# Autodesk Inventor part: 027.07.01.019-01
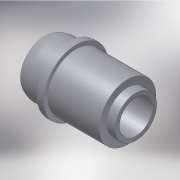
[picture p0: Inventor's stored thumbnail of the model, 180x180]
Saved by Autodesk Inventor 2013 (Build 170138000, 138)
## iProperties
Shininess: 25.0
Length Units: 11269
Angle Units: 11279
Time Units: 11290
Mass Units: 11283
Length Display Precision: 3
Angle Display Precision: 2
Created: 2001-11
Part Number: 027.07.01.019-01
Document SubType Name: Modeling
Designer: SOleg
Material: Steel, Mild
Density: 7.86 g/cm^3
Density: 0.0
Volumn: 0.0
Area: 0.0
PropertySet Name: Model Information
Control State: 0
Master: False
Checked Out: True
Checked Out Date: 2008-10-15
Last Check In Date: 2008-10-15
Author: SOleg
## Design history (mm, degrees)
body "Solid1"
revolve "RevolutionAngle1" stored, may be unused: angle "d24" = 360 deg
sketch "Sketch1"
  geometry: L1 (-25.5, 16.5)-(-19.232, 16.5); L2 (-32.5, 14.624)-(-32.5, 10); L3 (-32.5, 10)-(22.5, 10); L4 (22.5, 12.5)-(22.5, 10); L5 (22.5, 12.5)-(17.5, 12.5); L6 (17.5, 12.5)-(17.5, 17); L7 (17.5, 17)-(-13.5, 17); L8 (-13.5, 17)-(-13.5, 19.5); L9 (-13.5, 19.5)-(-17.5, 19.5); L10 (-19.232, 16.5)-(-17.5, 19.5); L11 (-27.5, 0)-(27.5, 0); L12 (-27.5, 0)-(27.5, 0); A1 r 14 centre (-25.5, 2.5) between (-25.5, 16.5) and (-32.5, 14.624)
  constraints: 24 end point, 6 horizontal, 4 vertical, 2 point on circle, 1 centre point, 1 other
  dimensions: "d1" = 55 distance of L2.end L3.end; "d3" = 19.5 vertical distance of L9.end L11.start; "d5" = 17 vertical distance of L6.end L11.end; "d7" = 12.5 vertical distance of L4.start L11.end; "d9" = 10 vertical distance of L3.end L11.end; "d11" = 120 deg angle of L10 L9; "d13" = 7 horizontal distance of L2.end A1.centre; "d15" = 4 distance of L8.end L9.end; "d17" = 19 horizontal distance of L7.end L2.end; "d19" = 14 radius of A1; "d21" = 16.5 vertical distance of L1.start L11.start; "d23" = 5 distance of L4.start L5.end
other parameters: "d0" = 55 (derived), "d2" = 19.5 (derived), "d4" = 17 (derived), "d6" = 15.5 (derived), "d10" = 120 deg (derived), "d12" = 7 (derived), "d14" = 4 (derived), "d16" = 19 (derived), "d18" = 14 (derived), "d20" = 16.5 (derived), "d22" = 5 (derived)
